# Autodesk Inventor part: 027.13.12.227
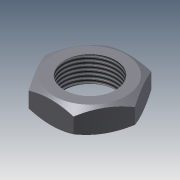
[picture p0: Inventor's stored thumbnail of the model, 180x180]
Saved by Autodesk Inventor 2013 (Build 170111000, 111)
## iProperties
Shininess: 64.0
Length Units: 11269
Angle Units: 11279
Time Units: 11290
Mass Units: 11283
Length Display Precision: 3
Angle Display Precision: 2
Created: 2002-02
Part Number: 027.13.12.227
Material: Steel, Mild
Document SubType Name: Modeling
Designer: SOleg
Density: 7.86 g/cm^3
Density: 0.0
Volumn: 0.0
Area: 0.0
PropertySet Name: Model Information
Control State: 0
Master: False
Checked Out: True
Checked Out Date: 2008-10-15
Last Check In Date: 2008-10-15
Author: SOleg
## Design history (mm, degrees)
sketch "Sketch1" dims "d0" = 41
  geometry: L1 (11.836, 20.5)-(23.671, 0); L2 (23.671, 0)-(11.836, -20.5); L3 (11.836, -20.5)-(-11.836, -20.5); L4 (-11.836, -20.5)-(-23.671, 0); L5 (-23.671, 0)-(-11.836, 20.5); L6 (-11.836, 20.5)-(11.836, 20.5); C1 r 13.5 at (0, 0); 3 further points
  constraints: 12 end point, 1 centre point, 1 coincident, 1 midpoint, 1 vertical alignment, 14 other
  dimensions: "d3" = 27 diameter of C1
extrude "Extrusion1" new body sketch "Sketch1" distance "d1" = 13.5; taper "d2" = 0 deg
sketch "Sketch2"
  geometry: L1 (-23.671, 0)-(-23.671, 13.5) reference; L2 (-23.671, 6.75)-(22.312, 6.75); L3 (-24.386, 13.5)-(-19, 13.5); L4 (-19, 13.5)-(-24.386, 10.391); L5 (-24.386, 10.391)-(-24.386, 13.5); L6 (-11.836, 13.5)-(-23.671, 13.5) reference; L7 (11.836, 13.5)-(-11.836, 13.5) reference; L8 (0, 13.5)-(0, -0.037); L9 (-19, 13.5)-(-19, 12.078); L10 (-19, 0)-(-24.386, 3.109); L11 (-24.386, 3.109)-(-24.386, 0); L12 (-24.386, 0)-(-19, 0)
  constraints: 18 end point, 3 perpendicular, 3 symmetric about line, 2 midpoint, 2 parallel, 1 collinear, 3 other
  dimensions: "d4" = 38 diameter of L9 L8; "d5" = 30 deg angle of L4 L3
revolve "Revolution1" sketch "Sketch2" stored, may be unused: angle "d6" = 90 deg
thread "Thread1" dims "d7" = 10, "d8" = 0
body "Solid1"
